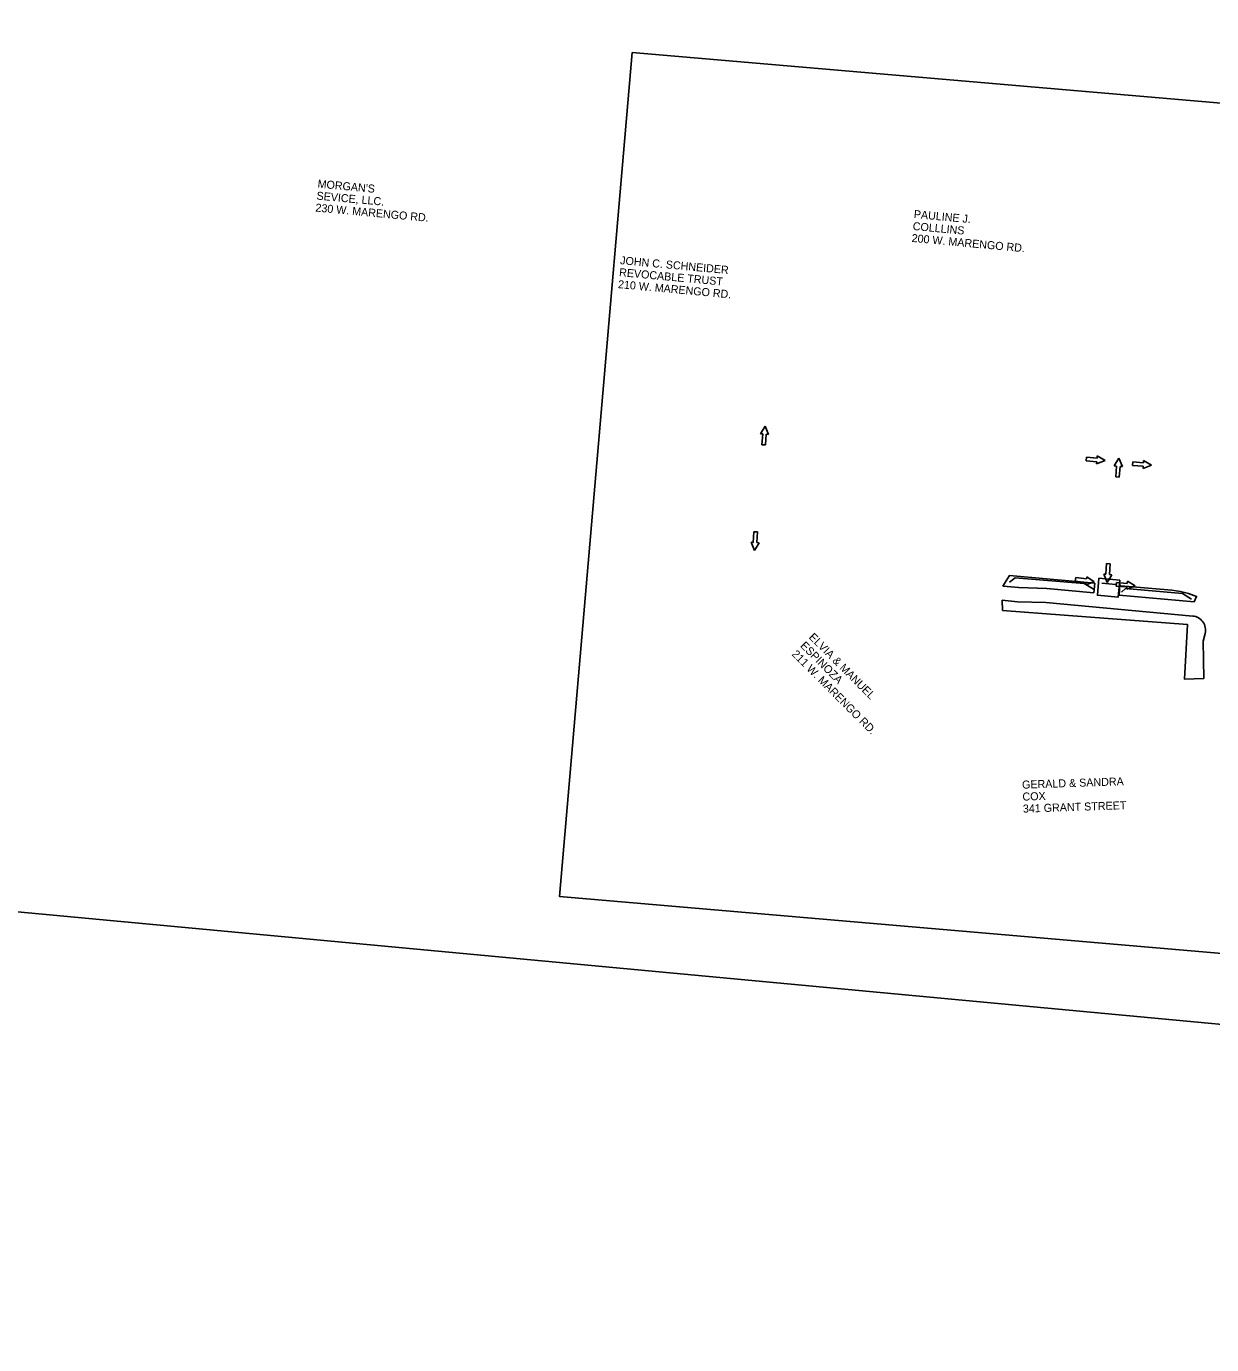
# Model space of a CAD drawing. Extents: x 20499351 to 20505779, y 7953198 to 7954637.
# Drawn here: x 20500144.5 to 20500564.2, y 7953706.6 to 7954173.4 of the extents above; entities that cross this region are included whole.
import ezdxf

# ---------------------------------------------------------------- set-up
doc = ezdxf.new("R2010")
doc.units = 0
for name, color, linetype in [('_CIVIL_CONSTRUCTION', 7, 'Continuous'), ('Contours Major', 7, 'Continuous'), ('Contours Minor', 7, 'Continuous'), ('NamedBoundary', 7, 'Continuous'), ('Terrain', 7, 'Continuous'), ('TL_GroundIntercept', 7, 'Continuous')]:
    doc.layers.add(name, color=color, linetype=linetype)

msp = doc.modelspace()

# ---------------------------------------------------------------- linework, layer by layer
at = {"layer": '_CIVIL_CONSTRUCTION'}
for p, q in [((20500404.42, 7954029.15), (20500406.06, 7954031.9)), ((20500406.06, 7954031.9), (20500407.28, 7954028.93)), ((20500405.22, 7954029.09), (20500404.42, 7954029.15)), ((20500404.93, 7954025.28), (20500405.22, 7954029.09)), ((20500406.2, 7954025.19), (20500404.93, 7954025.28)), ((20500406.48, 7954028.99), (20500406.2, 7954025.19)), ((20500407.28, 7954028.93), (20500406.48, 7954028.99)), ((20500519.7, 7954019.57), (20500519.81, 7954020.84)), ((20500519.81, 7954020.84), (20500523.61, 7954020.52)), ((20500523.61, 7954020.52), (20500523.68, 7954021.32)), ((20500523.68, 7954021.32), (20500526.41, 7954019.65)), ((20500529.7, 7954017.77), (20500531.34, 7954020.51)), ((20500531.34, 7954020.51), (20500532.55, 7954017.55)), ((20500523.51, 7954019.26), (20500519.7, 7954019.57)), ((20500526.41, 7954019.65), (20500523.44, 7954018.46)), ((20500523.44, 7954018.46), (20500523.51, 7954019.26)), ((20500530.49, 7954017.71), (20500529.7, 7954017.77)), ((20500530.2, 7954013.9), (20500530.49, 7954017.71)), ((20500531.76, 7954017.61), (20500531.47, 7954013.81)), ((20500532.55, 7954017.55), (20500531.76, 7954017.61)), ((20500536.14, 7954017.89), (20500536.22, 7954019.16)), ((20500539.95, 7954017.64), (20500536.14, 7954017.89)), ((20500536.22, 7954019.16), (20500540.03, 7954018.91)), ((20500542.84, 7954018.09), (20500539.9, 7954016.85)), ((20500539.9, 7954016.85), (20500539.95, 7954017.64)), ((20500540.03, 7954018.91), (20500540.08, 7954019.71)), ((20500540.08, 7954019.71), (20500542.84, 7954018.09)), ((20500531.47, 7954013.81), (20500530.2, 7954013.9)), ((20500401.88, 7953990.66), (20500402.11, 7953994.47)), ((20500402.11, 7953994.47), (20500403.38, 7953994.4)), ((20500403.38, 7953994.4), (20500403.15, 7953990.59)), ((20500402.34, 7953987.77), (20500401.08, 7953990.71)), ((20500401.08, 7953990.71), (20500401.88, 7953990.66)), ((20500403.94, 7953990.54), (20500402.34, 7953987.77)), ((20500403.15, 7953990.59), (20500403.94, 7953990.54)), ((20500526.75, 7953979.38), (20500526.99, 7953983.19)), ((20500526.99, 7953983.19), (20500528.26, 7953983.11)), ((20500528.26, 7953983.11), (20500528.02, 7953979.3)), ((20500519.86, 7953977.75), (20500519.97, 7953978.53)), ((20500519.97, 7953978.53), (20500522.61, 7953976.73)), ((20500527.2, 7953976.48), (20500525.96, 7953979.43)), ((20500525.96, 7953979.43), (20500526.75, 7953979.38)), ((20500528.81, 7953979.25), (20500527.2, 7953976.48)), ((20500528.02, 7953979.3), (20500528.81, 7953979.25)), ((20500515.9, 7953977.01), (20500516.08, 7953978.27)), ((20500519.68, 7953976.49), (20500515.9, 7953977.01)), ((20500516.08, 7953978.27), (20500519.86, 7953977.75)), ((20500522.61, 7953976.73), (20500519.57, 7953975.7)), ((20500519.57, 7953975.7), (20500519.68, 7953976.49)), ((20500530.37, 7953975.23), (20500530.47, 7953976.5)), ((20500534.17, 7953974.91), (20500530.37, 7953975.23)), ((20500530.47, 7953976.5), (20500534.28, 7953976.18)), ((20500537.07, 7953975.31), (20500534.1, 7953974.12)), ((20500534.1, 7953974.12), (20500534.17, 7953974.91)), ((20500534.28, 7953976.18), (20500534.34, 7953976.97)), ((20500534.34, 7953976.97), (20500537.07, 7953975.31))]:
    msp.add_line(p, q, dxfattribs=at)
at = {"layer": 'Contours Major'}
for p, q in [((20500495.74, 7953974.69), (20500490.34, 7953975.18)), ((20500531.67, 7953975.69), (20500531.38, 7953972.01)), ((20500561.87, 7953958.44), (20500561.2, 7953955.7))]:
    msp.add_line(p, q, dxfattribs=at)
for points in [[(20500522.84, 7953976.26), (20500505.69, 7953977.77), (20500492.56, 7953978.94), (20500490.24, 7953975.19)], [(20500490.24, 7953975.19), (20500490.49, 7953975.17), (20500495.88, 7953974.68), (20500505.76, 7953974.36), (20500522.44, 7953972.83), (20500522.84, 7953976.26)], [(20500531.38, 7953972.01), (20500557.92, 7953969.58), (20500558.82, 7953971.55), (20500556.02, 7953972.62), (20500553.13, 7953973.33), (20500550.06, 7953973.76), (20500536.23, 7953974.91), (20500531.92, 7953975.35), (20500531.67, 7953975.69)], [(20500490.11, 7953966.61), (20500490.01, 7953970.19), (20500495.43, 7953969.69), (20500505.44, 7953969.36), (20500557.46, 7953964.6)], [(20500561.2, 7953955.7), (20500561.4, 7953942.54), (20500554.5, 7953942.3), (20500555.56, 7953961.65), (20500490.11, 7953966.61)]]:
    msp.add_lwpolyline(points, dxfattribs=at)
msp.add_arc((20500557, 7953959.62), 5, 346.4397, 84.7647, dxfattribs=at)
at = {"layer": 'Contours Minor'}
msp.add_line((20500525.28, 7953976.27), (20500530.26, 7953975.82), dxfattribs=at)
for points in [[(20500492.64, 7953976.59), (20500494.61, 7953978.15), (20500519.02, 7953976.17), (20500522.55, 7953973.98)], [(20500532.21, 7953973.07), (20500533.62, 7953974.41), (20500553.86, 7953972.57), (20500557.04, 7953970.6)]]:
    msp.add_lwpolyline(points, dxfattribs=at)
msp.add_lwpolyline([(20500524.27, 7953977.96), (20500531.61, 7953977.3), (20500531.08, 7953971.32), (20500523.73, 7953971.98)], close=True, dxfattribs=at)
at = {"layer": 'NamedBoundary'}
msp.add_lwpolyline([(20500359.01, 7954164.14), (20500333.3, 7953865.25), (20501270.32, 7953784.65), (20501296.03, 7954083.54)], close=True, dxfattribs=at)
at = {"layer": 'Terrain'}
msp.add_lwpolyline([(20501791.06, 7953833.84), (20501779.66, 7953706.56), (20499351.13, 7953933.78), (20499411.85, 7954636.65), (20501855.07, 7954405.25), (20501814.1, 7954091.19), (20501791.1, 7953834.34)], dxfattribs=at)

# ---------------------------------------------------------------- texts
at = {"layer": 'TL_GroundIntercept'}
for s, height, rotation, p in [("MORGAN'S ", 2.835, 354.7645, (20500247.54, 7954116.35)), ('SEVICE, LLC.', 2.8346, 354.7645, (20500247.15, 7954112.12)), ('230 W. MARENGO RD.', 2.8346, 354.7645, (20500246.77, 7954107.89)), ('PAULINE J.', 2.835, 354.7645, (20500458.63, 7954105.59)), ('200 W. MARENGO RD.', 2.8346, 354.7645, (20500457.86, 7954097.12)), ('COLLLINS', 2.835, 354.7645, (20500458.25, 7954101.35)), ('JOHN C. SCHNEIDER', 2.8346, 354.7645, (20500354.66, 7954089.24)), ('REVOCABLE TRUST', 2.8346, 354.7645, (20500354.28, 7954085.01)), ('210 W. MARENGO RD.', 2.8346, 354.7645, (20500353.89, 7954080.77)), ('ESPINOZA', 2.835, 314.9836, (20500418.32, 7953953.88)), ('ELVIA & MANUEL', 2.8346, 314.9836, (20500421.33, 7953956.88)), ('211 W. MARENGO RD.', 2.8346, 314.9836, (20500415.31, 7953950.87)), ('GERALD & SANDRA', 2.8346, 1.9645, (20500497.09, 7953903.45)), ('COX', 2.835, 1.9645, (20500497.23, 7953899.21)), ('341 GRANT STREET', 2.8346, 1.9645, (20500497.38, 7953894.96))]:
    msp.add_text(s, height=height, rotation=rotation, dxfattribs=at).set_placement(p)

doc.saveas('drawing.dxf')
